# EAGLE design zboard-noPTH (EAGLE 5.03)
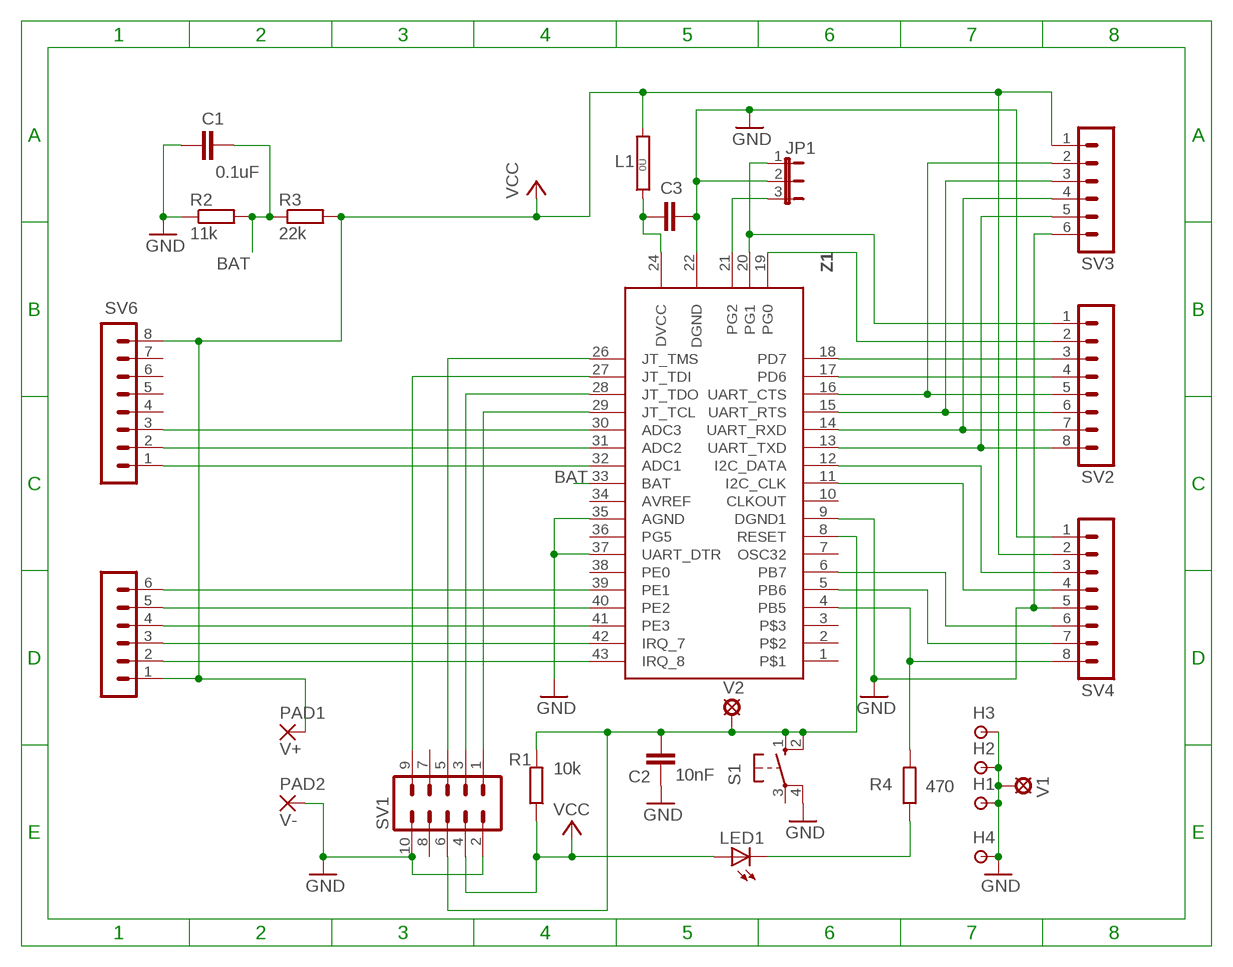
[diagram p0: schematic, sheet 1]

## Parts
C1  0.1uF  C5P  [C050-030-075]
C2  10nF  C5P  [C050-030-075]
C3  10uF 10V ceramic  CSMT0805  [C0805]
H1  HOLE/SMALL  [1,6/0,8]
H2  HOLE/SMALL  [1,6/0,8]
H3  HOLE/SMALL  [1,6/0,8]
H4  HOLE/SMALL  [1,6/0,8]
JP1  3 way pin header with jumper  JP2E  [JP2]
L1  Ferrite bead  0R  [0R/10]
LED1  red LED  LED-3MM3MM  [HLMP-D105]
PAD1  V+  TERMINAL-PAD  [2,54/1,1]
PAD2  V-  TERMINAL-PAD  [2,54/1,1]
R1  10k  R  [0207/10]
R2  11k  R  [0207/10]
R3  22k  R  [0207/10]
R4  470  R  [0207/10]
S1  BW-1000 pushbutton  10-XX  [B3F-10XX]
SV1  10 way IDC male header  ML10  [ML10]
SV2  8 way pin header bottom mount  MA08-1  [MA08-1]
SV3  6 way pin header bottom mount  MA06-1  [MA06-1]
SV4  8 way pin header bottom mount  MA08-1  [MA08-1]
SV5  6 way pin header bottom mount  MA06-1  [MA06-1]
SV6  8 way pin header bottom mnt  MA08-1  [MA08-1]
V1  HOLE/VIA  [LSP10]
V2  HOLE-VIA  [LSP10]
Z1  ZDM-A1281-A2N  [ZIGSMD]

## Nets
BAT: C1.2 R2.2 R3.1 Z1.33(BAT)
GND: C1.1 C2.1 C3.2 H1.1(P) H2.1(P) H3.1(P) H4.1(P) JP1.2 PAD2.1(P) R2.1 S1.4(P1) SV1.2 SV1.10 SV3.6 SV4.1 SV4.5 V1.MP Z1.9(DGND1) Z1.22(DGND) Z1.35(AGND) Z1.37(UART_DTR)
N$3: SV6.2 Z1.31(ADC2)
N$4: SV6.3 Z1.30(ADC3)
N$5: SV6.1 Z1.32(ADC1)
N$7: SV5.4 Z1.41(PE3)
N$9: SV1.5 Z1.26(JT_TMS)
N$10: SV1.1 Z1.29(JT_TCL)
N$11: SV1.3 Z1.28(JT_TDO)
N$12: SV5.6 Z1.39(PE1)
N$13: C2.2 R1.2 S1.1(S) S1.2(S1) SV1.6 V2.MP Z1.8(RESET)
N$14: SV5.3 Z1.42(IRQ_7)
N$15: SV5.2 Z1.43(IRQ_8)
N$16: SV2.3 Z1.18(PD7)
N$17: SV2.4 Z1.17(PD6)
N$18: SV2.5 SV3.2 Z1.16(UART_CTS)
N$19: SV2.6 SV3.3 Z1.15(UART_RTS)
N$20: SV2.7 SV3.4 Z1.14(UART_RXD)
N$21: SV2.8 SV3.5 Z1.13(UART_TXD)
N$22: SV4.3 Z1.12(I2C_DATA)
N$23: SV4.4 Z1.11(I2C_CLK)
N$24: SV2.2 Z1.19(PG0)
N$25: JP1.1 SV2.1 Z1.20(PG1)
N$26: SV4.6 Z1.6(PB7)
N$27: SV4.7 Z1.5(PB6)
N$28: R4.2 SV4.8 Z1.4(PB5)
N$29: JP1.3 Z1.21(PG2)
N$30: LED1.K(C) R4.1
N$31: SV1.9 Z1.27(JT_TDI)
N$32: SV5.5 Z1.40(PE2)
N$33 [supply]: C3.1 L1.1 Z1.24(DVCC)
VCC: L1.2 LED1.A PAD1.1(P) R1.1 R3.2 SV1.4 SV3.1 SV4.2 SV5.1 SV6.8
Unconnected: S1.3(P) SV1.7 SV1.8 SV6.4 SV6.5 SV6.6 SV6.7 Z1.1 Z1.2 Z1.3 Z1.7(OSC32) Z1.10(CLKOUT) Z1.34(AVREF) Z1.36(PG5) Z1.38(PE0)

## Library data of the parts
C1-C3 = ee2parts:C: Capacitor
H1-H4 = ee2parts:HOLE/SMALL: SMALL THROUGH-HOLE PAD/TESTPOINT
JP1 = jumper:JP2E: JUMPER
L1 = jumper:0R: Bridge 0R 10mm
LED1 = ee2parts:LED-3MM: LED
PAD1 PAD2 = ee2parts:TERMINAL-PAD: LARGE THROUGH-HOLE PAD
R1-R4 = ee2parts:R: Resistor
S1 = switch-omron:10-XX: OMRON SWITCH
SV1 = con-harting-ml:ML10: HARTING
SV2 SV4 SV6 = con-lstb:MA08-1: PIN HEADER
SV3 SV5 = con-lstb:MA06-1: PIN HEADER
V1 = ee2parts:HOLE/VIA: FIXED VIA
V2 = ee2parts:HOLE-VIA: FIXED VIA
Z1 = ee2parts:ZDM-A1281-A2

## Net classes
1 supply: width 0.635 mm

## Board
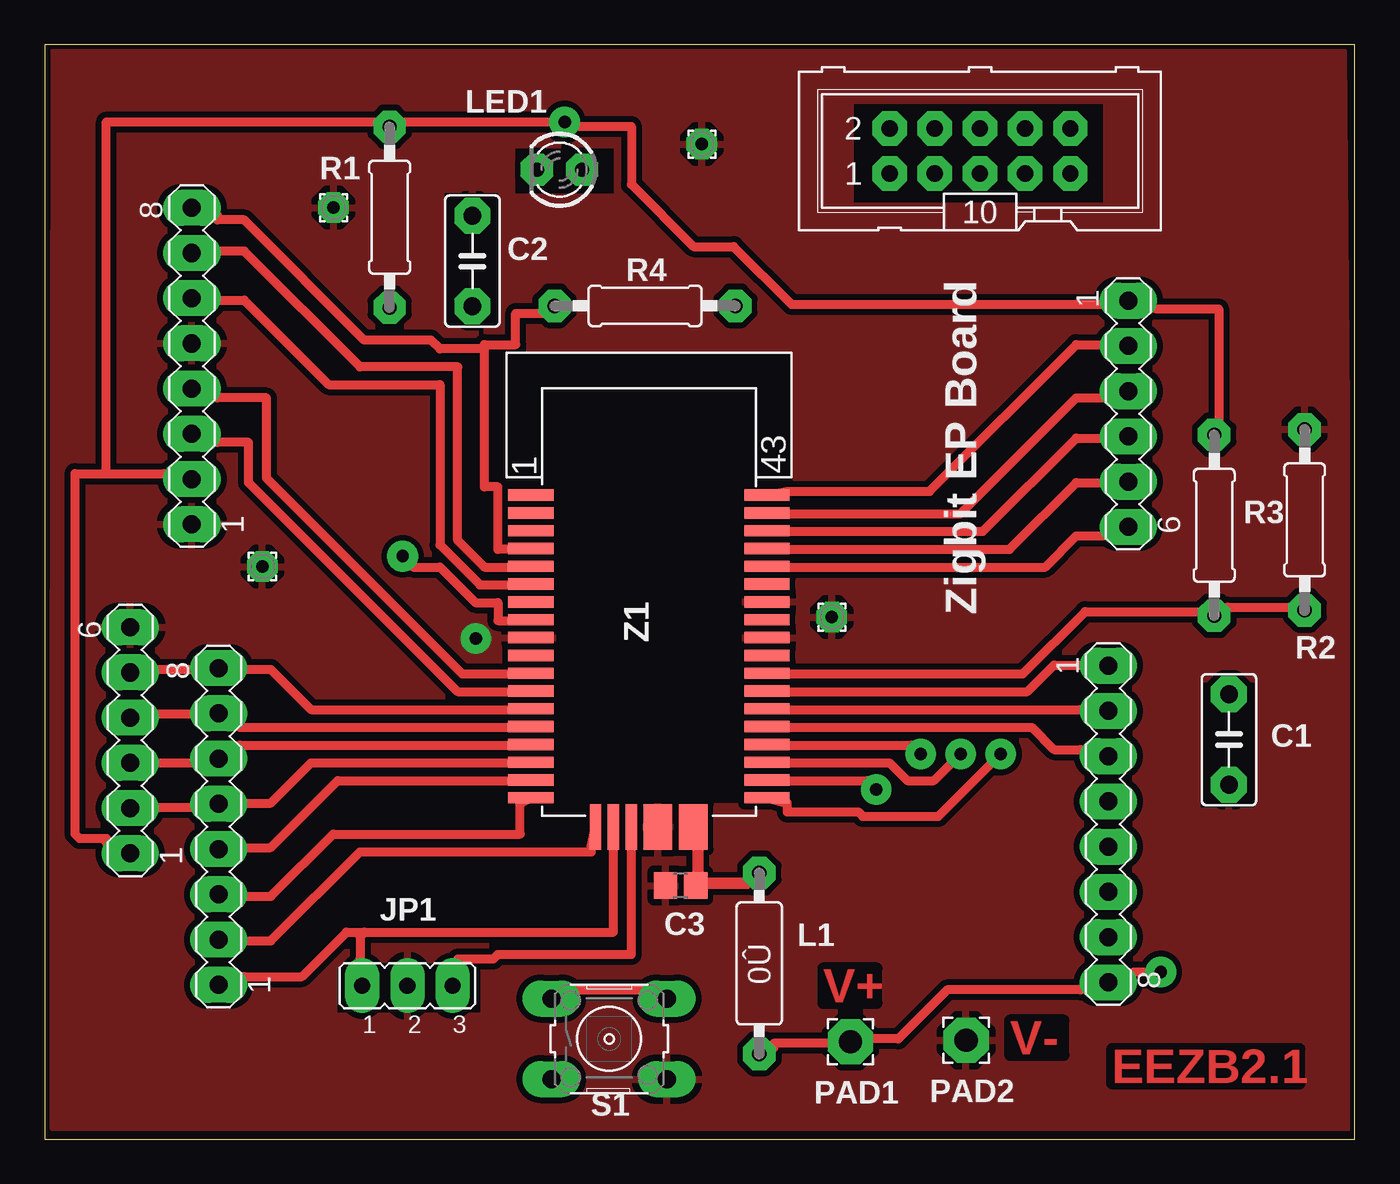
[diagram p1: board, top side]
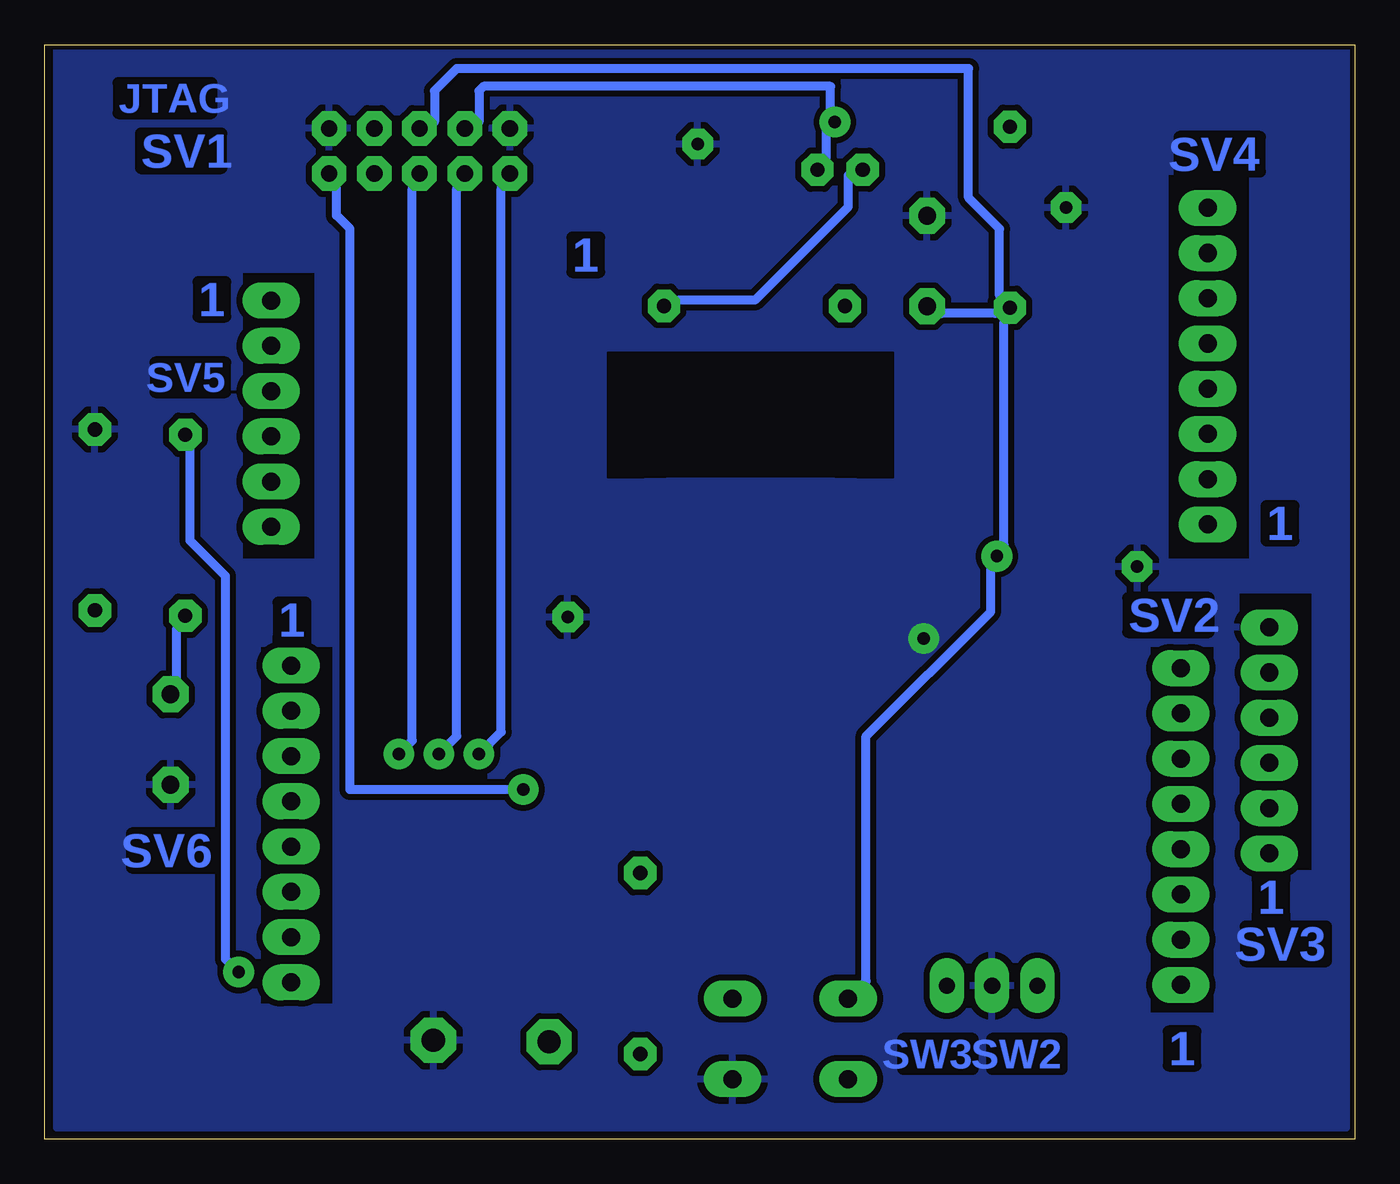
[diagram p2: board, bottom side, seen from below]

Size 73.63 x 61.48 mm. Coordinates in mm from the lower left corner, seen from the top.
Outline: 0,0 73.63,0 73.63,61.48 0,61.48 0,0
Copper layers (1*16): Top 0.035mm / dielectric 1.5mm / Bottom 0.035mm
Design rules "zigbit_rules *": minimum track width 20mil, minimum drill 0.7mm, track to track 13mil, track to pad 13mil, pad to pad 13mil, via to via 13mil, smd to smd 0mil, copper to edge 10mil, drill to drill 10mil, minimum pad ring 20mil, minimum via ring 20mil, stop-mask expansion 0mil, vias tented up to drill 0mil, thermal gap 15mil
tRestrict: area 45.5,52.6 to 59.5,58.1; area 16.5,7.1 to 24.5,9.6; area 65,18.6 to 68,25.6; area 26.5,53.1 to 32,55.6; area 22.5,45.6 to 25.5,53.1
bRestrict: area 6,32.6 to 10.5,54.1; area 8,7.1 to 11.5,27.6; area 2.5,15.1 to 6.5,30.6; area 58.5,32.6 to 62.5,48.6; area 57.5,7.6 to 61.5,27.6
vRestrict: area 18,29.1 to 26,31.6; area 18.5,25.6 to 23,29.1; area 21,31.1 to 25,34.1; area 42,50.6 to 63.5,60.6

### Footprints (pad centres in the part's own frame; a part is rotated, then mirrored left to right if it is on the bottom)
C050-030-075 = drill 1 octagon: 1 -2.54,0; 2 2.54,0
C0805 = smd 1.3 x 1.5: 1 -0.85,0; 2 0.85,0
1,6/0,8 = drill 0.7 pad 1.6 octagon: 1 0,0
JP2 = drill 0.914 long: 1 -2.54,0; 2 0,0; 3 2.54,0
0R/10 = drill 0.813 pad 1.6 octagon: 1 -5.08,0; 2 5.08,0
HLMP-D105 = drill 0.8 octagon: A -1.27,0; K 1.27,0
2,54/1,1 = drill 1.3 pad 2.54 octagon: 1 0,0
0207/10 = drill 0.8 octagon: 1 -5.08,0; 2 5.08,0
B3F-10XX = drill 1.016 long: 1 -3.251,2.261; 2 3.251,2.261; 3 -3.251,-2.261; 4 3.251,-2.261
ML10 = drill 0.914 octagon: 1 -5.08,-1.27; 2 -5.08,1.27; 3 -2.54,-1.27; 4 -2.54,1.27; 5 0,-1.27; 6 0,1.27; 7 2.54,-1.27; 8 2.54,1.27; 9 5.08,-1.27; 10 5.08,1.27
MA08-1 = drill 1.016 long: 1 -8.89,0; 2 -6.35,0; 3 -3.81,0; 4 -1.27,0; 5 1.27,0; 6 3.81,0; 7 6.35,0; 8 8.89,0
MA06-1 = drill 1.016 long: 1 -6.35,0; 2 -3.81,0; 3 -1.27,0; 4 1.27,0; 5 3.81,0; 6 6.35,0
LSP10 = drill 0.7 pad 1.016 round: MP 0,0
ZIGSMD = smd 0.635 x 2.54: 1 7,6.635; 2 6,6.635; 3 5,6.635; 4 4,6.635; 5 3,6.635; 6 2,6.635; 7 1,6.635; 8 0,6.635; 9 -1,6.635; 10 -2,6.635; 11 -3,6.635; 12 -4,6.635; 13 -5,6.635; 14 -6,6.635; 15 -7,6.635; 16 -8,6.635; 17 -9,6.635; 18 -10,6.635; 26 -10,-6.635; 27 -9,-6.635; 28 -8,-6.635; 29 -7,-6.635; 30 -6,-6.635; 31 -5,-6.635; 32 -4,-6.635; 33 -3,-6.635; 34 -2,-6.635; 35 -1,-6.635; 36 0,-6.635; 37 1,-6.635; 38 2,-6.635; 39 3,-6.635; 40 4,-6.635; 41 5,-6.635; 42 6,-6.635; 43 7,-6.635 | smd 2.54 x 0.635: 19 -11.635,3; 20 -11.635,2; 21 -11.635,1 | smd 2.54 x 1.6: 22 -11.635,-0.5; 24 -11.635,-2.5

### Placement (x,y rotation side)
C1  66.55,22.44 90 top
C2  24.04,49.32 270 top
C3  35.74,14.25 180 top
H1  44.24,29.32 0 top
H2  36.94,55.89 0 top
H3  12.24,32.16 0 top
H4  16.24,52.32 0 top
JP1  20.39,8.62 0 top
L1  40.16,9.87 270 top
LED1  28.93,54.45 180 top
PAD1  45.28,5.47 0 top
PAD2  51.78,5.55 0 top
R1  19.39,51.78 270 top
R2  70.8,34.78 270 top
R3  65.72,34.48 90 top
R4  33.74,46.8 180 top
S1  31.73,5.63 0 top
SV1  52.56,55.5 0 top
SV2  9.78,17.56 90 top
SV3  4.82,22.4 90 top
SV4  8.28,43.42 90 top
SV5  60.89,40.74 270 top
SV6  59.77,17.7 270 top
V1  24.24,28.13 0 top
V2  20.12,32.74 0 top
Z1  33.96,29.17 90 top

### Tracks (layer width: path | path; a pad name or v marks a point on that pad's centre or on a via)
BAT
  Top 0.508: Z1.33 41.72,26.13 54.97,26.13 58.47,29.63 64.97,29.63 R3.1 66.47,29.88 69.97,29.88 R2.2
  Bottom 0.508: C1.2 66.22,25.88 66.22,28.63 R3.1
GND
  pour Bottom: 0.47,61.13 72.97,61.13 72.97,0.63 0.47,0.63
  pour Top: 0.53,61.13 72.97,61.13 73.47,0.63 0.47,0.63
N$3
  Top 0.508: Z1.31 41.72,24.13 58.22,24.13 SV6.2
N$4
  Top 0.508: Z1.30 41.72,23.13 55.47,23.13 56.72,21.88 58.22,21.88 SV6.3
N$5
  Top 0.508: Z1.32 41.72,25.13 55.22,25.13 56.72,26.63 58.22,26.63 SV6.1
N$7
  Top 0.508: Z1.41 41.72,34.13 52.72,34.13 57.97,39.38 59.47,39.38 SV5.4
N$9  (via drill 0.7)
  Top 0.508: v53.72,21.63 50.22,18.13 45.97,18.13 45.72,18.38 41.72,18.38 41.72,18.88 Z1.26
  Bottom 0.508: v53.72,21.63 52.97,22.38 52.97,53.38 SV1.5
N$10  (via drill 0.7)
  Top 0.508: v49.22,21.63 48.72,22.13 41.72,22.13 Z1.29
  Bottom 0.508: v49.22,21.63 47.97,22.88 47.97,53.38 SV1.1
N$11  (via drill 0.7)
  Top 0.508: v51.47,21.63 49.97,20.13 48.47,20.13 47.47,21.13 41.72,21.13 Z1.28
  Bottom 0.508: v51.47,21.63 50.47,22.63 50.47,53.38 SV1.3
N$12
  Top 0.508: Z1.39 41.72,32.13 56.22,32.13 57.97,33.88 59.47,33.88 SV5.6
N$13
  Top 0.508: S1.1 29.97,8.38 33.47,8.38 S1.2 | Z1.8 26.22,29.13 25.47,29.13 25.47,30.13 24.22,30.13 22.22,32.13 20.72,32.13 V2.MP
  Bottom 0.508: S1.1 27.47,8.88 27.47,22.63 20.47,29.63 20.47,32.13 V2.MP 19.72,33.38 19.72,45.88 R1.2 | R1.2 20.22,46.38 23.22,46.38 C2.2 | SV1.6 51.72,57.13 51.72,58.88 50.47,60.13 21.72,60.13 21.72,52.88 19.97,51.13 19.97,47.38 R1.2
N$14
  Top 0.508: Z1.42 41.72,35.13 51.47,35.13 57.97,41.63 59.47,41.63 SV5.3
N$15
  Top 0.508: Z1.43 41.72,36.38 49.72,36.38 57.97,44.63 59.47,44.63 SV5.2
N$16
  Top 0.508: Z1.18 26.72,18.88 26.72,17.13 16.22,17.13 12.72,13.63 11.22,13.63 SV2.3
N$17
  Top 0.508: Z1.17 26.22,20.13 16.47,20.13 12.72,16.38 11.22,16.38 SV2.4
N$18
  Top 0.508: Z1.16 26.22,21.13 14.97,21.13 12.72,18.88 11.22,18.88 SV2.5 8.22,18.63 6.22,18.63 SV3.2
N$19
  Top 0.508: Z1.15 26.22,22.13 10.97,22.13 SV2.6 8.22,21.13 SV3.3
N$20
  Top 0.508: Z1.14 26.22,23.13 10.97,23.13 SV2.7 8.22,23.88 6.22,23.88 SV3.4
N$21
  Top 0.508: Z1.13 26.22,24.13 14.97,24.13 12.72,26.38 11.22,26.38 SV2.8 8.22,26.38 6.22,26.38 SV3.5
N$22
  Top 0.508: Z1.12 26.22,25.13 23.22,25.13 11.47,36.88 11.47,39.13 9.72,39.13 SV4.3
N$23
  Top 0.508: Z1.11 26.22,26.13 23.47,26.13 12.47,37.13 12.47,41.63 9.72,41.63 SV4.4
N$24
  Top 0.508: Z1.19 30.72,16.38 30.72,16.13 17.72,16.13 12.72,11.13 11.22,11.13 SV2.2
N$25
  Top 0.508: 17.97,11.63 31.97,11.63 31.97,16.38 Z1.20 | 17.97,11.63 17.72,11.38 17.72,10.13 JP1.1 | SV2.1 11.22,9.13 14.47,9.13 16.97,11.63 17.97,11.63
N$26
  Top 0.508: Z1.6 26.22,31.13 24.47,31.13 22.22,33.38 22.22,42.38 15.97,42.38 11.22,47.13 9.72,47.13 SV4.6
N$27
  Top 0.508: Z1.5 26.22,32.13 24.72,32.13 23.22,33.63 23.22,43.38 17.72,43.38 11.22,49.88 9.72,49.88 SV4.7
N$28
  Top 0.508: 24.72,44.38 24.72,44.63 26.47,44.63 26.47,46.38 27.97,46.38 R4.2 | 24.72,44.38 24.72,36.63 25.47,36.63 25.47,33.13 26.22,33.13 Z1.4 | SV4.8 9.72,51.88 9.72,51.63 11.22,51.63 17.97,44.88 21.72,44.88 22.22,44.38 24.72,44.38
N$29
  Top 0.508: Z1.21 32.97,16.38 32.97,10.38 25.47,10.38 25.22,10.13 23.22,10.13 JP1.3
N$30
  Bottom 0.508: LED1.K 28.47,54.13 28.47,52.38 33.72,47.13 37.97,47.13 R4.1
N$31  (via drill 0.7)
  Top 0.508: v46.72,19.63 46.22,20.13 41.72,20.13 Z1.27
  Bottom 0.508: v46.72,19.63 56.47,19.63 56.47,51.13 57.22,51.88 57.22,53.38 SV1.9
N$32
  Top 0.508: Z1.40 41.72,33.13 54.22,33.13 57.97,36.88 59.47,36.88 SV5.5
N$33
  Top 0.635: Z1.24 36.72,16.38 36.72,14.88 C3.1 37.22,14.38 39.47,14.38 L1.1
VCC  (via drill 0.7)
  Top 0.508: 3.47,37.38 6.72,37.38 SV4.2 | 3.47,37.38 1.72,37.38 1.72,17.13 1.97,16.88 3.47,16.88 3.47,16.63 SV3.1 | L1.2 40.97,5.13 40.97,5.38 44.22,5.38 PAD1.1 46.47,5.63 47.97,5.63 50.72,8.38 58.22,8.38 SV6.8 61.22,9.38 v62.72,9.38 | R3.2 65.97,40.38 65.97,46.63 62.47,46.63 SV5.1 59.47,46.88 41.97,46.88 38.72,50.13 36.47,50.13 32.97,53.63 32.97,56.88 29.97,56.88 v29.22,57.13 20.22,57.13 R1.1 18.72,57.13 3.47,57.13 3.47,37.38
  Bottom 0.508: LED1.A 29.72,55.13 29.72,56.63 v29.22,57.13 29.47,57.88 29.47,59.13 48.97,59.13 49.22,58.88 49.22,57.13 SV1.4 | v62.72,9.38 63.47,10.13 63.47,31.63 65.47,33.63 65.47,38.88 R3.2

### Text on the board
Top: EEZB2.1
Bottom: JTAG | 1 | 1 | SV5 | 1 | 1 | 1 | SW2 | SW3 | 1
tPlace: Zigbit EP Board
